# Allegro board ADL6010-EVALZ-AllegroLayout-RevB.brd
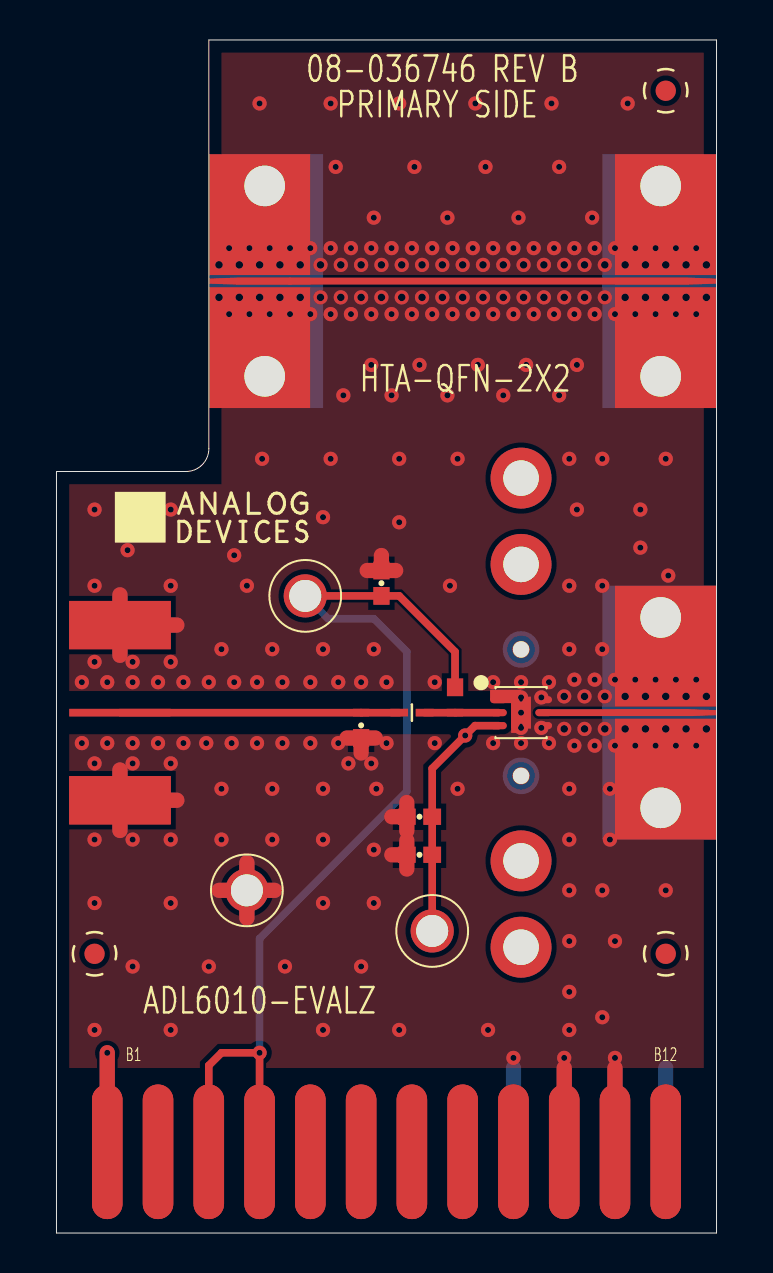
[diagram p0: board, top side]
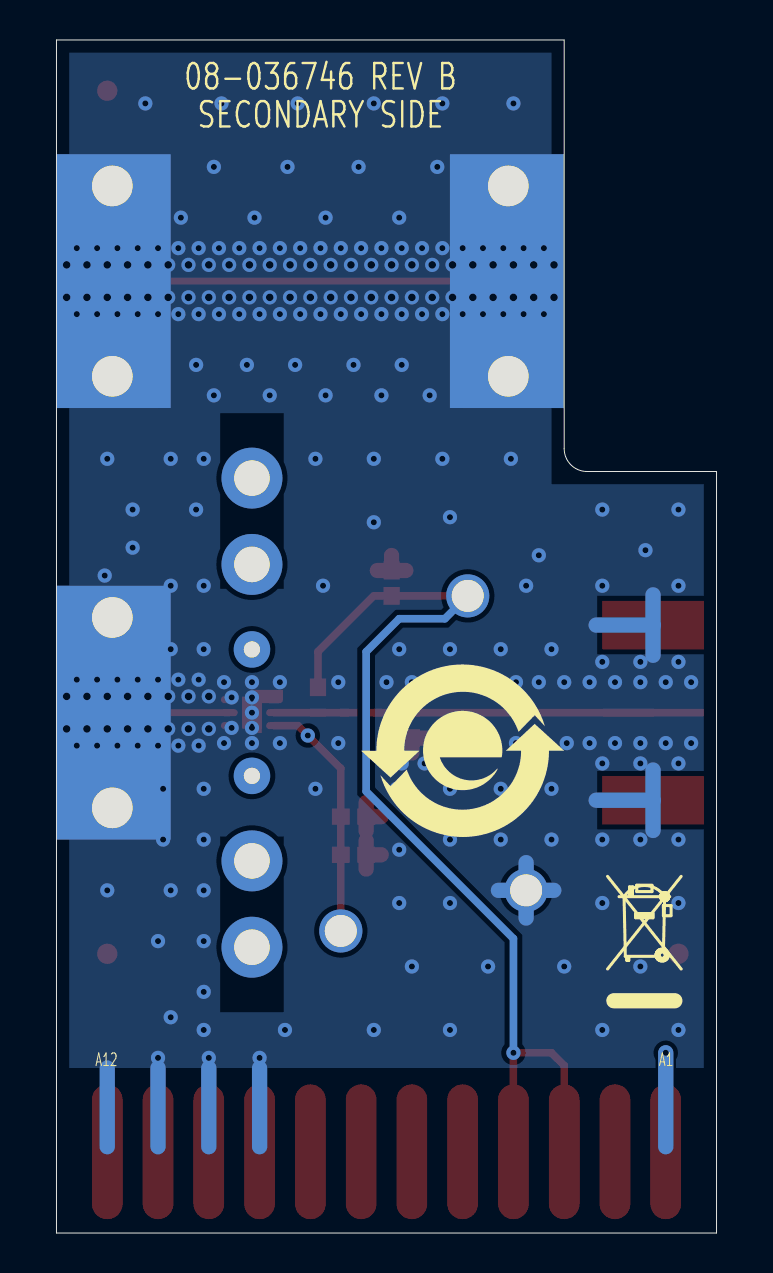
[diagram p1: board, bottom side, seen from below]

Outline 33.02 x 59.69 mm; copper layers: TOP, L2_PLANE, L3_PLANE, BOTTOM. Coordinates in mm from the lower left corner of the outline.
Outline path: 0,38.1 0,0 33.02,0 33.02,59.69 7.62,59.69 7.62,39.24 arc(7.29,38.43) 6.48,38.1 0,38.1

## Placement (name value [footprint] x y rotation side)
C1  TBD0402  [C0402]  15.24 25.4 270 top
C2  TBD0402  [C0402]  16.26 32.51 90 top
C3  0.1UF  [C0402]  18.16 18.92 180 top
C4  100pF  [C0402]  18.16 20.83 0 top
GND  BLK  [CNLOOPTP]  9.53 17.15 0 top
J1  1092-04A-5  [CNSMAL700W500H290]  32.6 47.62 0 top
J2  1092-04A-5  [CNSMAL700W500H290]  8.04 47.62 180 top
NOREF  -  []  -264.54 -223.52 0 top
NOREF#2  -  []  33.02 0 90 top
NOREF#3  -  []  15.88 69.85 0 top
NOREF#4  -  []  0 0 90 top
NOREF#5  -  []  0 38.1 90 top
NOREF#6  -  []  175.26 179.7 0 top
NOREF#7  -  []  33.02 59.69 180 top
NOREF#8  -  []  72.39 29.21 0 top
NOREF#9  -  []  0 0 0 top
NOREF#10  -  []  -101.09 -107.19 0 top
NOREF#11  -  []  0 0 0 top
NOREF#12  -  []  30.23 52.39 90 top
NOREF#13  -  []  7.62 52.45 0 top
NOREF#14  -  []  189.86 99.06 270 top
NOREF#15  -  []  -12.7 -46.36 0 top
NOREF#16  -  [unnamed#2]  1.9 13.97 0 top
NOREF#17  -  []  15.75 59.69 270 top
NOREF#18  -  []  76.33 -15.88 0 top
NOREF#19  -  []  0 0 0 top
NOREF#20  -  []  -254 -274.32 0 top
NOREF#21  -  []  7.62 59.69 0 top
NOREF#22  -  [unnamed#2]  30.48 57.15 0 top
NOREF#23  -  []  -198.12 -79.38 0 top
NOREF#24  -  []  2.92 34.54 0 top
NOREF#25  -  []  0 38.1 270 top
NOREF#26  -  []  30.23 52.39 0 top
NOREF#27  -  [unnamed#2]  30.48 13.97 0 top
NOREF#28  -  [unnamed#3]  23.24 26.04 0 top
NOREF#29  -  []  -144.15 -116.2 0 top
NOREF#30  -  []  38.73 5.08 0 top
NOREF#31  -  []  7.32 38.47 0 top
NOREF#32  -  []  38.73 -12.06 0 top
NOREF#33  -  []  12.7 24.13 180 bottom
NOREF#34  -  []  3.81 11.3 180 bottom
P1  NCFINGER_2X12P_A  [FINGER2X12P_A]  16.51 4.06 0 top
R1  100  [R0402]  17.78 26.04 180 top
R2  100  [R0402]  19.94 26.67 270 top
RFIN  1092-04A-5  [CNSMAL700W500H290]  32.6 26.04 0 top
U1  ADL6010ACPZN  [UQFN6_2_05X2_05_PAD1_6X1_A]  23.24 26.04 270 top
V_OUT  WHT  [CNLOOPTP]  12.45 31.88 0 top
VOUT  JOHNSON142-0701-851  [CNJOHNSON142-0701-851]  3.18 26.04 180 top
VPOS  RED  [CNLOOPTP]  18.8 15.11 180 top

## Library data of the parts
C1 C2 = CAP: User Part Number: UPN; alternate symbols: (C0402H22_ALT,C0201-2,C0402_A,C0402_ALT); part number: CAP_SM-TBD0402,TBD0402,TBD0402,E000381,C0402
C3 = CAP: Tolerance: 10; User Part Number: UPN; alternate symbols: (C0402H22_ALT,C0201-2,C0402_A,C0402_ALT); part number: CAP_SM-0.1UF,16V,10,E007200,C0402; tolerance: 10
C4 = CAP: Tolerance: 5; User Part Number: UPN; alternate symbols: (C0402H22_ALT,C0201-2,C0402_A,C0402_ALT); part number: CAP_SM-100PF,50V,5,E007896,C0402; tolerance: 5
GND = CNTP1P: User Part Number: UPN; alternate symbols: (CNBANANA_ALT); part number: CNTP1P_TH-BLK,E000948,CNLOOPTP
J1 J2 RFIN = CNBNC3P: User Part Number: UPN; part number: CNBNC3P_SM-1092-04A-5,E016488,SOUTHWEST MICROWAVE,1092-04A-5,SCD-015702,CNSMAL700W500H290
P1 = NCFINGER_2X12P: User Part Number: UPN; part number: NCFINGER_2X12P_SM-NCFINGER_2X12P_A,E007699,FINGER2X12P_A
R1 R2 = RES: Tolerance: 0.1; User Part Number: UPN; alternate symbols: (RRAD984L1500W75H520LD32;TO220H590_ALT;R0402_A;R0603_A); part number: RES_SM-100,E006692,1/16W,0.1,SUSUMU,RG1005P-101-B-T5,SCD-002134,R0402,N/A; tolerance: 0.1
U1 = ADL6010: User Part Number: UPN; alternate symbols: (UQFN6_2_05X2_05_PAD1_6X1); part number: ADL6010_SM-ADL6010ACPZN,E019839,UQFN6_2_05X2_05_PAD1_6X1_A,N/A
V_OUT = CNTP1P: User Part Number: UPN; alternate symbols: (CNBANANA_ALT); part number: CNTP1P_TH-WHT,E000946,CNLOOPTP
VOUT = CNBNC5P: User Part Number: UPN; alternate symbols: (CNAMPHENOL132255-11_ALT); part number: CNBNC5P_SM-JOHNSON142-0701-851,E000923,JOHNSON,142-0701-851,SCD-010536,CNJOHNSON142-0701-851
VPOS = CNTP1P: User Part Number: UPN; alternate symbols: (CNBANANA_ALT); part number: CNTP1P_TH-RED,E000947,CNLOOPTP

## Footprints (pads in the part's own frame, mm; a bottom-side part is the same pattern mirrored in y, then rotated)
C0402
  rect 0.889x0.813 smd: 1(-0.635,0) 2(0.635,0)
CNJOHNSON142-0701-851
  rect 5.08x0.381 smd: 1(0,0)
  rect 5.08x2.413 smd: 2(0,4.381) 3(0,4.381) 4(0,-4.381) 5(0,-4.381)
CNLOOPTP
  round 2.159 hole 1.6: 1(0,0)
CNSMAL700W500H290
  round 0.203 smd: 1(-1.016,0)
  round 2.54 hole 2.032: 2(-2.375,4.763) 3(-2.375,-4.763)
FINGER2X12P_A
  oval 1.524x6.731 smd: A1(-13.97,0.254) A2(-11.43,0.254) A3(-8.89,0.254) A4(-6.35,0.254) A5(-3.81,0.254) A6(-1.27,0.254) A7(1.27,0.254) A8(3.81,0.254) A9(6.35,0.254) A10(8.89,0.254) A11(11.43,0.254) A12(13.97,0.254) B1(-13.97,0) B2(-11.43,0) B3(-8.89,0) B4(-6.35,0) B5(-3.81,0) B6(-1.27,0) B7(1.27,0) B8(3.81,0) B9(6.35,0) B10(8.89,0) B11(11.43,0) B12(13.97,0)
R0402
  rect 0.889x0.813 smd: 1(-0.635,0)
  rect 0.381x0.813 smd: 2(0.635,0)
unnamed#2
  round 1.016 smd: (0,0)
unnamed#3
  round 3.048 hole 1.778 unplated: (0,11.735) (0,7.417) (0,-7.417) (0,-11.735)
  round 0.864 hole 0.813 unplated: (0,3.162) (0,-3.162)
UQFN6_2_05X2_05_PAD1_6X1_A
  oval 0.356x0.838 smd: 1(-0.65,-1.131) 2(0,-1.131) 3(0.65,-1.131) 4(0.65,1.131) 5(0,1.131) 6(-0.65,1.131)
  rect 1.6x0.991 smd: PAD(0,0)

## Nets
GND: C1.2(N2) C2.2(N2) C3.2(N2) C4.1(N1) GND.1(N1) J1.2(SH1) J1.3(SH2) J2.2(SH1) J2.3(SH2) P1.A9(N9) P1.A10(N10) P1.A11(N11) P1.A12(N12) P1.B10(N10) P1.B11(N11) RFIN.2(SH1) RFIN.3(SH2) U1.1(GND1) U1.4(GND2) U1.6(GND3) U1.PAD VOUT.2(SH1) VOUT.3(SH2) VOUT.4(SH3) VOUT.5(SH4)
UNNAMED_2_ADL6010_I42_RFIN: RFIN.1(CNTR) U1.5(RFIN)
UNNAMED_2_ADL6010_I42_VOUT: R1.1(N1) R2.2(N2) U1.2(VOUT)
UNNAMED_2_CAP_I49_N1: C1.1(N1) R1.2(N2) VOUT.1(CNTR)
UNNAMED_2_CNBNC3P_I26_CNTR: J1.1(CNTR) J2.1(CNTR)
V_OUT: C2.1(N1) P1.B3(N3) P1.B4(N4) R2.1(N1) V_OUT.1(N1)
VPOS: C3.1(N1) C4.2(N2) P1.A1(N1) P1.B1(N1) U1.3(VPOS) VPOS.1(N1)

Pads without a net: P1 A2 A3 A4 A5 A6 A7 A8 B2 B5 B6 B7 B8 B9 B12

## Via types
v1: diameter 0.711, hole 0.305, TOP to BOTTOM, 204 vias
v2: diameter 0.711, hole 0.381, TOP to BOTTOM, 66 vias
v3: diameter 0.356, hole 0.178, TOP to BOTTOM, 3 vias

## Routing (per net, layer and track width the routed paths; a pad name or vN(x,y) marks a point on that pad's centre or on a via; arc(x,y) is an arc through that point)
GND: length 67.4
  TOP w0.762: 14.53,24.77 C1.2 ; C1.2 15.24,24.02 ; C1.2 15.95,24.77 ; 3.18,28.9 3.18,30.42 ; 3.18,30.42 3.18,31.93 ; 3.18,30.42 6.02,30.42 ; 17.53,18.21 C3.2 ; C3.2 16.78,18.92 ; C3.2 17.53,19.63 ; 17.53,20.12 C4.1 ; C4.1 17.53,21.54 ; C4.1 16.78,20.83 ; VOUT.2 6.02,21.65 ; VOUT.2 3.18,20.14 ; VOUT.2 3.18,23.17 ; C2.2 16.97,33.15 ; C2.2 16.26,33.9 ; C2.2 15.54,33.15 ; GND.1 9.53,18.53 ; GND.1 10.91,17.15 ; GND.1 9.53,15.76 ; GND.1 8.14,17.15 ; P1.B11 27.94,8.26 ; P1.B10 25.4,8.26
  BOTTOM w0.762: 3.18,30.42 6.02,30.42 ; 3.18,30.42 3.18,31.93 ; 3.18,30.42 3.18,28.9 ; VOUT.2 6.02,21.65 ; VOUT.2 3.18,20.14 ; VOUT.2 3.18,23.17 ; GND.1 10.91,17.15 ; GND.1 8.14,17.15 ; GND.1 9.53,15.76 ; GND.1 9.53,18.53 ; P1.A11 27.94,8.26 ; P1.A12 30.48,8.26 ; P1.A9 22.86,8.26 ; P1.A10 25.4,8.26
  vias: v1(1.27,27.56) v1(1.27,24.51) v1(1.9,36.2) v1(1.9,32.39) v1(1.9,28.58) v1(1.9,23.5) v1(1.9,19.69) v1(1.9,16.51) v1(1.9,10.16) v1(2.54,27.56) v1(2.54,24.51) v1(3.56,34.16) v1(3.81,28.58) v1(3.81,27.56) v1(3.81,24.51) v1(3.81,23.5) v1(3.81,19.69) v1(3.81,13.34) v1(5.08,27.56) v1(5.08,24.51) v1(5.71,36.2) v1(5.71,32.39) v1(5.71,28.58) v1(5.71,23.5) v1(5.71,19.69) v1(5.71,16.51) v1(5.71,10.16) v1(6.35,27.56) v1(6.35,24.51) v1(7.49,24.51) v1(7.62,27.56) v1(7.62,13.34) v1(8.26,29.21) v1(8.26,22.23) v1(8.26,19.69) v1(8.64,49.28) v1(8.64,45.97) v1(8.76,24.51) v1(8.89,33.91) v1(8.89,27.56) v1(9.53,32.39) v1(9.65,49.28) v1(9.65,45.97) v1(10.03,27.56) v1(10.03,24.51) v1(10.16,56.52) v1(10.29,38.73) v1(10.67,49.28) v1(10.67,45.97) v1(10.79,29.21) v1(10.79,22.23) v1(10.79,19.69) v1(11.3,27.56) v1(11.3,24.51) v1(11.43,13.34) v1(11.68,49.28) v1(11.68,45.97) v1(12.7,49.28) v1(12.7,45.97) v1(12.7,27.56) v1(12.7,24.51) v1(13.34,35.81) v1(13.34,29.21) v1(13.34,22.23) v1(13.34,19.69) v1(13.34,16.51) v1(13.34,10.16) v1(13.72,56.52) v1(13.72,49.28) v1(13.72,45.97) v1(13.72,38.73) v1(13.97,53.34) v1(14.1,27.56) v1(14.1,24.51) v1(14.35,41.91) v1(14.61,23.5) v1(14.73,49.28) v1(14.73,45.97) v1(15.24,27.56) v1(15.24,13.34) v1(15.75,49.28) v1(15.75,45.97) v1(15.75,43.43) v1(15.75,23.5) v1(15.88,50.8) v1(15.88,29.21) v1(15.88,19.18) v1(15.88,16.51) v1(16,22.23) v1(16.51,27.56) v1(16.51,24.51) v1(16.76,49.28) v1(16.76,45.97) v1(16.76,41.91) v1(17.14,56.52) v1(17.14,38.73) v1(17.14,35.56) v1(17.14,10.16) v1(17.78,49.28) v1(17.78,45.97) v1(17.91,53.34) v1(18.16,43.43) v1(18.8,49.28) v1(18.8,45.97) v1(18.92,27.56) v1(18.92,24.51) v1(19.56,50.8) v1(19.56,41.91) v1(19.68,32.39) v1(19.81,49.28) v1(19.81,45.97) v1(20.07,38.73) v1(20.07,22.23) v1(20.83,49.28) v1(20.83,45.97) v1(20.96,56.52) v1(21.08,43.43) v1(21.46,53.34) v1(21.59,10.16) v1(21.84,49.28) v1(21.84,45.97) v1(21.84,27.56) v1(21.84,24.51) v1(22.35,41.91) v1(22.86,49.28) v1(22.86,45.97) v1(22.86,8.76) v1(23.11,50.8) v1(23.24,27.56) v1(23.24,26.8) v1(23.24,26.04) v1(23.24,25.27) v1(23.24,24.51) v1(23.5,43.43) v1(23.88,49.28) v1(23.88,45.97) v1(24.26,26.8) v1(24.26,25.27) v1(24.64,27.56) v1(24.64,24.51) v1(24.77,56.52) v1(24.89,49.28) v1(24.89,45.97) v1(25.15,53.34) v1(25.15,41.91) v1(25.4,8.76) v1(25.65,38.73) v1(25.65,32.39) v1(25.65,29.21) v1(25.65,22.23) v1(25.65,19.69) v1(25.65,17.15) v1(25.65,14.61) v1(25.65,12.07) v1(25.65,10.16) v1(25.91,49.28) v1(25.91,45.97) v1(25.91,27.69) v1(25.91,24.38) v1(26.04,43.43) v1(26.04,36.2) v1(26.8,50.8) v1(26.92,49.28) v1(26.92,45.97) v1(26.92,27.69) v1(26.92,24.38) v1(27.3,38.73) v1(27.3,32.39) v1(27.3,29.21) v1(27.3,17.15) v1(27.3,10.8) v1(27.69,22.23) v1(27.69,19.69) v1(27.94,49.28) v1(27.94,45.97) v1(27.94,27.69) v1(27.94,24.38) v1(27.94,14.61) v1(27.94,8.76) v1(28.57,56.52) v1(28.96,49.28) v1(28.96,45.97) v1(28.96,27.69) v1(28.96,24.38) v1(29.21,36.2) v1(29.21,34.29) v1(29.97,49.28) v1(29.97,45.97) v1(29.97,27.69) v1(29.97,24.38) v1(30.48,38.73) v1(30.48,17.15) v1(30.61,32.89) v1(30.99,49.28) v1(30.99,45.97) v1(30.99,27.69) v1(30.99,24.38) v1(32,49.28) v1(32,45.97) v1(32,27.69) v1(32,24.38) v2(8.13,48.44) v2(8.13,46.81) v2(9.15,48.44) v2(9.15,46.81) v2(10.16,48.44) v2(10.16,46.81) v2(11.18,48.44) v2(11.18,46.81) v2(12.19,48.44) v2(12.19,46.81) v2(13.21,48.44) v2(13.21,46.81) v2(14.22,48.44) v2(14.22,46.81) v2(15.24,48.44) v2(15.24,46.81) v2(16.26,48.44) v2(16.26,46.81) v2(17.27,48.44) v2(17.27,46.81) v2(18.29,48.44) v2(18.29,46.81) v2(19.3,48.44) v2(19.3,46.81) v2(20.32,48.44) v2(20.32,46.81) v2(21.34,48.44) v2(21.34,46.81) v2(22.35,48.44) v2(22.35,46.81) v2(23.37,48.44) v2(23.37,46.81) v2(24.38,48.44) v2(24.38,46.81) v2(25.4,48.44) v2(25.4,46.81) v2(25.4,26.85) v2(25.4,25.22) v2(26.42,48.44) v2(26.42,46.81) v2(26.42,26.85) v2(26.42,25.22) v2(27.43,48.44) v2(27.43,46.81) v2(27.43,26.85) v2(27.43,25.22) v2(28.45,48.44) v2(28.45,46.81) v2(28.45,26.85) v2(28.45,25.22) v2(29.46,48.44) v2(29.46,46.81) v2(29.46,26.85) v2(29.46,25.22) v2(30.48,48.44) v2(30.48,46.81) v2(30.48,26.85) v2(30.48,25.22) v2(31.5,48.44) v2(31.5,46.81) v2(31.5,26.85) v2(31.5,25.22) v2(32.51,48.44) v2(32.51,46.81) v2(32.51,26.85) v2(32.51,25.22) v3(23.24,26.67) v3(23.24,26.04) v3(23.24,25.4)
UNNAMED_2_ADL6010_I42_RFIN: length 7.2
  TOP w0.343: RFIN.1 24.37,26.04
UNNAMED_2_ADL6010_I42_VOUT: length 3.7
  TOP w0.381: 18.41,26.04 R2.2 U1.2
UNNAMED_2_CAP_I49_N1: length 14
  TOP w0.381: 17.14,26.04 C1.1 VOUT.1
UNNAMED_2_CNBNC3P_I26_CNTR: length 22.5
  TOP w0.343: J1.1 J2.1
V_OUT: length 51.9
  TOP w0.381: P1.B4 v1(10.16,9.02) 8.26,9.02 7.62,8.38 P1.B3 ; V_OUT.1 C2.1 17.14,31.88 19.94,29.08 R2.1
  BOTTOM w0.381: V_OUT.1 13.59,30.73 15.88,30.73 17.53,29.08 17.53,22.1 10.16,14.73 v1(10.16,9.02)
VPOS: length 22
  TOP w0.381: VPOS.1 C3.1 C4.2 18.8,23.24 v1(20.45,24.89) 20.94,25.39 U1.3
  TOP w0.762: P1.B1 v1(2.54,9.02)
  BOTTOM w0.762: P1.A1 v1(2.54,9.02)

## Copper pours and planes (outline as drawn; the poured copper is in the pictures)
GND on TOP (solid shape): 12.7,47.93 7.62,47.93 7.62,53.98 12.7,53.98
GND on TOP (solid shape): 12.7,41.28 7.62,41.28 7.62,47.32 12.7,47.32
GND on TOP (solid shape): 33.02,47.93 27.94,47.93 27.94,53.98 33.02,53.98
GND on TOP (solid shape): 33.02,41.28 27.94,41.28 27.94,47.32 33.02,47.32
GND on TOP (solid shape): 33.02,26.34 27.94,26.34 27.94,32.39 33.02,32.39
GND on TOP (solid shape): 33.02,19.69 27.94,19.69 27.94,25.73 33.02,25.73
GND on TOP (solid shape): 23.24,25.02 22.75,25.02 22.75,26.51 21.88,26.51 21.69,26.7 21.69,27.18 23.24,27.18
GND on BOTTOM (solid shape): 13.34,41.28 7.62,41.28 7.62,53.98 13.34,53.98
GND on BOTTOM (solid shape): 33.02,41.28 27.3,41.28 27.3,53.98 33.02,53.98
GND on BOTTOM (solid shape): 33.02,19.69 27.3,19.69 27.3,32.39 33.02,32.39
GND on TOP: 0.64,8.26 0.64,37.46 8.26,37.46 8.26,41.28 12.7,41.28 12.7,53.98 8.26,53.98 8.26,59.05 32.38,59.05 32.38,53.98 27.94,53.98 27.94,41.28 32.38,41.28 32.38,32.39 27.94,32.39 27.94,19.69 32.38,19.69 32.38,8.26 ; 2 cut-outs
GND on BOTTOM: 0.64,8.26 0.64,37.46 8.26,37.46 8.26,41.28 13.34,41.28 13.34,53.98 8.26,53.98 8.26,59.05 32.38,59.05 32.38,53.98 27.3,53.98 27.3,41.28 32.38,41.28 32.38,32.39 27.3,32.39 27.3,19.69 32.38,19.69 32.38,8.26
GND on L2_PLANE: 0.64,0.64 0.64,37.46 8.26,37.46 8.26,41.28 7.62,41.28 7.62,53.97 8.26,53.97 8.26,59.05 32.38,59.05 32.38,53.97 33.02,53.97 33.02,41.28 32.38,41.28 32.38,32.38 33.02,32.38 33.02,19.69 32.38,19.69 32.38,0.64
GND on L3_PLANE: 8.26,45.21 8.26,53.97 8.26,53.97 8.26,59.05 32.38,59.05 32.38,53.97 32.38,53.97 32.38,45.21
UNNAMED_2_ADL6010_I42_RFIN on TOP (solid shape): 33.02,26.16 33.02,25.91 31.75,25.86 27.94,25.86 27.94,26.21 31.75,26.21
UNNAMED_2_CNBNC3P_I26_CNTR on TOP (solid shape): 12.7,47.45 8.89,47.45 7.62,47.5 7.62,47.75 8.89,47.8 12.7,47.8
UNNAMED_2_CNBNC3P_I26_CNTR on TOP (solid shape): 33.02,47.75 33.02,47.5 31.75,47.45 27.94,47.45 27.94,47.8 31.75,47.8
VPOS on L3_PLANE: 0.64,0.64 0.64,37.46 8.26,37.46 8.26,41.28 8.26,41.28 8.26,44.58 32.38,44.58 32.38,41.28 32.38,41.28 32.38,32.38 32.38,32.38 32.38,19.69 32.38,19.69 32.38,0.64 ; 1 cut-out

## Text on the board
Ref Des/Silkscreen Bottom: 08-036746 REV B | SECONDARY SIDE
Ref Des/Silkscreen Top: ADL6010-EVALZ | PRIMARY SIDE | 08-036746 REV B
PAGE_OUTLINE: B | CHANGE AS PER ECR#045449 | 03/14 | P.C.
DIMENSION: A | .03 X 45 CHAMFER 2PL | MAX | REF | +2/-0 MILS | SEE NOTE 15
DISPLAY_TOP: INCLUDE ADDITIONAL FORMATS AS REQUIRED | DSIZE2    for second fabrication sheet | DSIZEM    for 1 scale mirror assy sheet 2 | DSIZE2_3  for 1.5 scale assy sheet 1 | DSIZE2_3M for 1.5 scale mirror assy sheet 2 | DSIZE1_2  for 2 scale assy sheet 1 | DSIZE1_2M for 2 scale mirror assy sheet 2
User.12: 15.    INDICATED VIAS TO BE NON-CONDUCTIVE FILLED, GROUND FLUSH, | PRIOR TO OVERPLATING. | ISOLA 370HR
User.13: L2 PLANE | 08-      -07
User.14: L3 PLANE | 08-      -08
User.15: BUMPLET PRIMARY | 08-      -11
User.18: 1
User.22: CHANGE AS PER ECR#045449 | B | 06/13 | 03/14 | P.C.
User.27: 1 | FABRICATION | 09 | B
User.29: FIGURE | SIZE | 12.0 | 15.0 | 63.0 | 80.0 | 32.0 | 70.0 | PLATED | NON-PLATED | FINISHED HOLES IN MILS | ALL UNITS ARE IN MILS | QTY | 204 | 66 | 3 | 6 | 2 | 4 | TOLERANCE/NOTES
